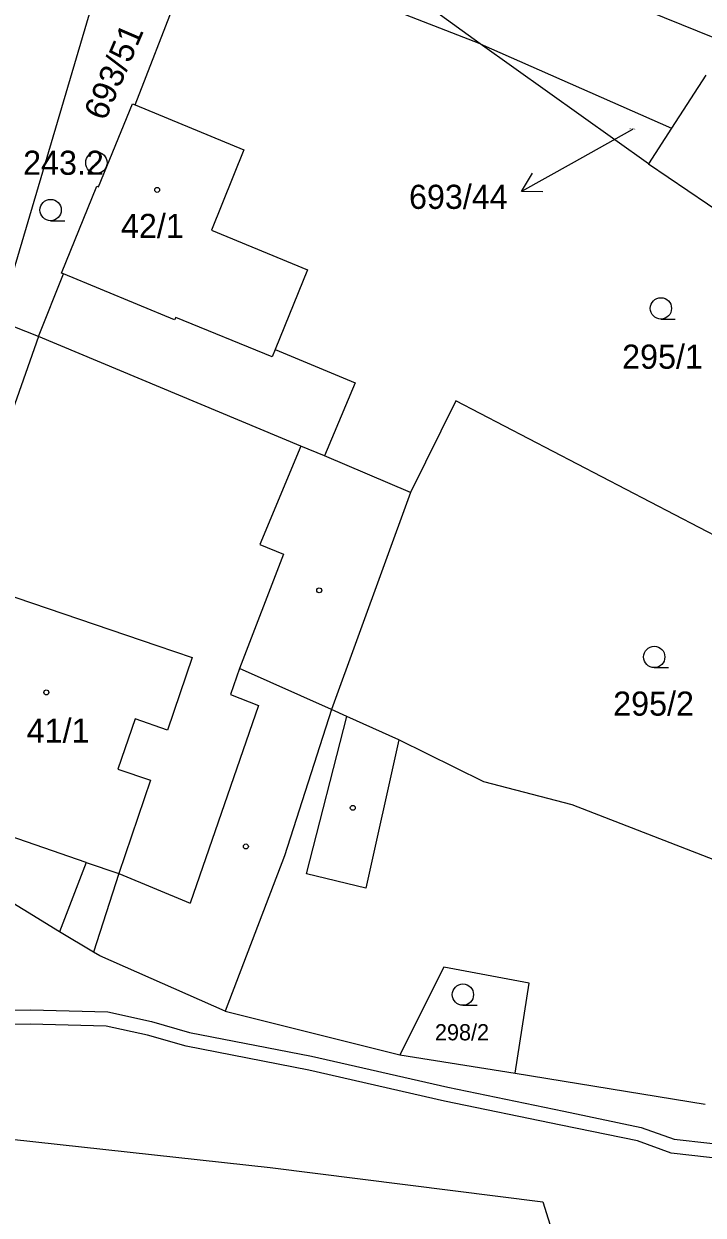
# Model space of a CAD drawing. Extents: x -747333 to -745433, y -1133152 to -1130600.
# Drawn here: x -746346.5 to -746298.7, y -1132218.2 to -1132134.3 of the extents above; entities that cross this region are included whole.
import ezdxf

# ---------------------------------------------------------------- set-up
doc = ezdxf.new("R2010")
doc.units = 0
for name, color, linetype in [('Vrstva 1', 7, 'Continuous'), ('Vrstva 16', 7, 'Continuous'), ('Vrstva 17', 7, 'Continuous'), ('Vrstva 18', 7, 'Continuous'), ('Vrstva 19', 7, 'Continuous'), ('Vrstva 24', 7, 'Continuous'), ('Vrstva 25', 7, 'Continuous'), ('Vrstva 3', 7, 'Continuous'), ('Vrstva 30', 7, 'Continuous'), ('Vrstva 37', 7, 'Continuous'), ('Vrstva 4', 7, 'Continuous')]:
    doc.layers.add(name, color=color, linetype=linetype)

msp = doc.modelspace()

# ---------------------------------------------------------------- linework, layer by layer
at = {"layer": 'Vrstva 1'}
for p, q in [((-746338.7, -1132140.02), (-746334.03, -1132128.06)), ((-746345.51, -1132156.33), (-746343.74, -1132151.93)), ((-746328.82, -1132157.26), (-746323.2, -1132159.6))]:
    msp.add_line(p, q, dxfattribs=at)
for points in [[(-746345.51, -1132156.33), (-746348.32, -1132155.23), (-746339.72, -1132126.2)], [(-746314.39, -1132135.73), (-746334.03, -1132128.06)], [(-746314.39, -1132135.73), (-746317.6, -1132133.4)], [(-746302.53, -1132144.17), (-746314.39, -1132135.73)], [(-746314.39, -1132135.73), (-746300.91, -1132141.67)], [(-746298.49, -1132137.94), (-746300.91, -1132141.67)], [(-746341.27, -1132145.79), (-746338.87, -1132139.95)], [(-746338.87, -1132139.95), (-746338.7, -1132140.02)], [(-746338.7, -1132140.02), (-746331.03, -1132143.2)], [(-746300.91, -1132141.67), (-746302.53, -1132144.17)], [(-746331.03, -1132143.2), (-746333.32, -1132148.85)], [(-746302.53, -1132144.17), (-746290.06, -1132152.64)], [(-746343.89, -1132151.87), (-746341.4, -1132145.74)], [(-746341.4, -1132145.74), (-746341.27, -1132145.79)], [(-746333.32, -1132148.85), (-746326.54, -1132151.64)], [(-746343.74, -1132151.93), (-746343.89, -1132151.87)], [(-746326.54, -1132151.64), (-746328.82, -1132157.26)], [(-746345.51, -1132156.33), (-746351.46, -1132173.24)], [(-746327.01, -1132164.06), (-746345.51, -1132156.33)], [(-746323.2, -1132159.6), (-746325.35, -1132164.75)], [(-746316.09, -1132160.88), (-746319.28, -1132167.34)], [(-746276.66, -1132181.4), (-746316.09, -1132160.88)], [(-746325.35, -1132164.75), (-746327.01, -1132164.06)], [(-746319.28, -1132167.34), (-746325.35, -1132164.75)], [(-746319.28, -1132167.34), (-746324.85, -1132182.62)], [(-746324.85, -1132182.62), (-746328.16, -1132192.93)], [(-746323.77, -1132183.11), (-746324.85, -1132182.62)], [(-746320.12, -1132184.74), (-746323.77, -1132183.11)], [(-746314.12, -1132187.7), (-746320.12, -1132184.74)], [(-746307.91, -1132189.33), (-746314.12, -1132187.7)], [(-746286.03, -1132197.8), (-746307.91, -1132189.33)], [(-746344.02, -1132198.28), (-746357.46, -1132190.03)], [(-746342.14, -1132193.39), (-746349.97, -1132190.7)], [(-746328.16, -1132192.93), (-746332.36, -1132203.87)], [(-746342.14, -1132193.39), (-746344.02, -1132198.28)], [(-746341.62, -1132199.71), (-746344.02, -1132198.28)], [(-746341.17, -1132199.97), (-746341.62, -1132199.71)], [(-746332.36, -1132203.87), (-746341.17, -1132199.97)], [(-746316.94, -1132200.77), (-746320.04, -1132206.95)], [(-746310.94, -1132201.9), (-746316.94, -1132200.77)], [(-746311.91, -1132208.23), (-746310.94, -1132201.9)], [(-746332.36, -1132203.87), (-746320.04, -1132206.95)], [(-746320.04, -1132206.95), (-746311.91, -1132208.23)], [(-746311.91, -1132208.23), (-746298.54, -1132210.41)], [(-746349.14, -1132212.69), (-746329.17, -1132214.87)], [(-746329.17, -1132214.87), (-746309.97, -1132217.3)], [(-746309.97, -1132217.3), (-746308.1, -1132223.28)]]:
    msp.add_lwpolyline(points, dxfattribs=at)
at = {"layer": 'Vrstva 16'}
msp.add_line((-746309.959741, -1132146.153177), (-746311.460448, -1132146.133657), dxfattribs=at)
for points in [[(-746303.64, -1132141.76), (-746307.97, -1132144.18)], [(-746307.97, -1132144.18), (-746311.460448, -1132146.133657), (-746310.692363, -1132144.84426)]]:
    msp.add_lwpolyline(points, dxfattribs=at)
at = {"layer": 'Vrstva 24'}
msp.add_line((-746341.47, -1132144.1), (-746341.37, -1132144.1), dxfattribs=at)
msp.add_circle((-746341.42, -1132144.1), 0.756017, dxfattribs=at)
at = {"layer": 'Vrstva 25'}
for p, q in [((-746344.65, -1132148.18), (-746343.65, -1132148.18)), ((-746301.65, -1132155.11), (-746300.65, -1132155.11)), ((-746302.12, -1132179.66), (-746301.12, -1132179.66)), ((-746315.6, -1132203.45), (-746314.6, -1132203.45))]:
    msp.add_line(p, q, dxfattribs=at)
for centre, radius in [((-746337.14, -1132146.01), 0.174503), ((-746344.65, -1132147.43), 0.75), ((-746301.65, -1132154.36), 0.75), ((-746325.72, -1132174.22), 0.174503), ((-746302.12, -1132178.91), 0.75), ((-746344.95, -1132181.41), 0.174503), ((-746323.36, -1132189.54), 0.174503), ((-746330.89, -1132192.26), 0.174503), ((-746315.6, -1132202.7), 0.75)]:
    msp.add_circle(centre, radius, dxfattribs=at)
at = {"layer": 'Vrstva 3'}
for points in [[(-746341.27, -1132145.79), (-746338.87, -1132139.95)], [(-746338.87, -1132139.95), (-746338.7, -1132140.02)], [(-746338.7, -1132140.02), (-746331.03, -1132143.2)], [(-746331.03, -1132143.2), (-746333.32, -1132148.85)], [(-746343.89, -1132151.87), (-746341.4, -1132145.74)], [(-746341.4, -1132145.74), (-746341.27, -1132145.79)], [(-746333.32, -1132148.85), (-746326.54, -1132151.64)], [(-746343.74, -1132151.93), (-746343.89, -1132151.87)], [(-746335.91, -1132155.17), (-746343.74, -1132151.93)], [(-746326.54, -1132151.64), (-746328.82, -1132157.26)], [(-746335.83, -1132154.99), (-746335.91, -1132155.17)], [(-746329.03, -1132157.78), (-746335.83, -1132154.99)], [(-746328.82, -1132157.26), (-746329.03, -1132157.78)], [(-746351.46, -1132173.24), (-746337.16, -1132178.1)], [(-746337.16, -1132178.1), (-746334.67, -1132178.95)], [(-746334.67, -1132178.95), (-746336.41, -1132184.06)], [(-746338.7, -1132183.28), (-746339.9, -1132186.81)], [(-746336.41, -1132184.06), (-746338.7, -1132183.28)], [(-746339.9, -1132186.81), (-746337.61, -1132187.59)], [(-746337.61, -1132187.59), (-746339.85, -1132194.17)], [(-746342.14, -1132193.39), (-746349.97, -1132190.7)], [(-746342.14, -1132193.39), (-746339.85, -1132194.17)]]:
    msp.add_lwpolyline(points, dxfattribs=at)
at = {"layer": 'Vrstva 30'}
for points in [[(-746352.67, -1132203.82), (-746346.06, -1132203.78)], [(-746346.06, -1132203.78), (-746340.62, -1132203.92)], [(-746340.62, -1132203.92), (-746337.55, -1132204.6)], [(-746346.08, -1132204.78), (-746352.65, -1132204.82)], [(-746340.74, -1132204.92), (-746346.08, -1132204.78)], [(-746337.55, -1132204.6), (-746334.86, -1132205.36)], [(-746337.81, -1132205.56), (-746340.74, -1132204.92)], [(-746335.09, -1132206.34), (-746337.81, -1132205.56)], [(-746334.86, -1132205.36), (-746326.26, -1132207.03)], [(-746326.46, -1132208.01), (-746335.09, -1132206.34)], [(-746326.26, -1132207.03), (-746316.67, -1132209.22)], [(-746316.89, -1132210.2), (-746326.46, -1132208.01)], [(-746316.67, -1132209.22), (-746308.5, -1132210.92)], [(-746308.7, -1132211.9), (-746316.89, -1132210.2)], [(-746308.5, -1132210.92), (-746303.04, -1132212.05)], [(-746303.31, -1132213.01), (-746308.7, -1132211.9)], [(-746303.04, -1132212.05), (-746300.71, -1132212.89)], [(-746300.93, -1132213.87), (-746303.31, -1132213.01)], [(-746300.71, -1132212.89), (-746295.7, -1132213.45)], [(-746295.74, -1132214.45), (-746300.93, -1132213.87)]]:
    msp.add_lwpolyline(points, dxfattribs=at)
at = {"layer": 'Vrstva 37'}
for centre in [(-746337.14, -1132146.01), (-746344.95, -1132181.41)]:
    msp.add_circle(centre, 0.174503, dxfattribs=at)
at = {"layer": 'Vrstva 4'}
for p, q in [((-746335.91, -1132155.17), (-746343.74, -1132151.93)), ((-746335.83, -1132154.99), (-746335.91, -1132155.17)), ((-746329.03, -1132157.78), (-746335.83, -1132154.99)), ((-746328.82, -1132157.26), (-746329.03, -1132157.78))]:
    msp.add_line(p, q, dxfattribs=at)
for points in [[(-746294.42, -1132136.7), (-746302.51, -1132133.44)], [(-746327.01, -1132164.06), (-746329.9, -1132170.98)], [(-746329.9, -1132170.98), (-746328.24, -1132171.67)], [(-746328.24, -1132171.67), (-746331.34, -1132179.73)], [(-746351.46, -1132173.24), (-746337.16, -1132178.1)], [(-746337.16, -1132178.1), (-746334.67, -1132178.95)], [(-746334.67, -1132178.95), (-746336.41, -1132184.06)], [(-746331.34, -1132179.73), (-746331.97, -1132181.56)], [(-746324.85, -1132182.62), (-746331.34, -1132179.73)], [(-746331.97, -1132181.56), (-746330, -1132182.34)], [(-746330, -1132182.34), (-746334.82, -1132196.26)], [(-746338.7, -1132183.28), (-746339.9, -1132186.81)], [(-746336.41, -1132184.06), (-746338.7, -1132183.28)], [(-746326.61, -1132194.2), (-746323.77, -1132183.11)], [(-746320.12, -1132184.74), (-746322.45, -1132195.19)], [(-746339.9, -1132186.81), (-746337.61, -1132187.59)], [(-746337.61, -1132187.59), (-746339.85, -1132194.17)], [(-746342.14, -1132193.39), (-746339.85, -1132194.17)], [(-746339.85, -1132194.17), (-746341.62, -1132199.71)], [(-746339.85, -1132194.17), (-746334.82, -1132196.26)], [(-746322.45, -1132195.19), (-746326.61, -1132194.2)]]:
    msp.add_lwpolyline(points, dxfattribs=at)

# ---------------------------------------------------------------- texts
at = {"layer": 'Vrstva 16'}
msp.add_text('693/44', height=1.7, dxfattribs=at).set_placement((-746319.396335, -1132147.35))
at = {"layer": 'Vrstva 17'}
msp.add_text('243.2', height=1.7, dxfattribs=at).set_placement((-746346.583695, -1132144.95))
at = {"layer": 'Vrstva 18'}
msp.add_text('693/51', height=1.7, rotation=66.81258, dxfattribs=at).set_placement((-746340.799447, -1132141.217172))
for s, height, p in [('693/44', 0.1, (-746303.869598, -1132141.76)), ('295/1', 1.7, (-746304.38, -1132158.61)), ('295/2', 1.7, (-746305.01, -1132183.05)), ('298/2', 1.14, (-746317.57, -1132205.92))]:
    msp.add_text(s, height=height, dxfattribs=at).set_placement(p)
at = {"layer": 'Vrstva 19'}
for s, p in [('42/1', (-746339.69, -1132149.4)), ('41/1', (-746346.33, -1132184.95))]:
    msp.add_text(s, height=1.7, dxfattribs=at).set_placement(p)

doc.saveas('drawing.dxf')
